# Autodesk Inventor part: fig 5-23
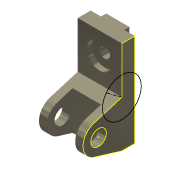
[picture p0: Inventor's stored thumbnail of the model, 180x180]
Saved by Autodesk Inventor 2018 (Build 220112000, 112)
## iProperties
Shininess: 65.0
Angle Display Precision: 2
Document Length Units: 11269
Document Angle Units: 11279
Document Time Units: 11290
Document Mass Units: 11283
Document Length Units Precision: 3
Document Angle Units Precision: 2
Compacted: False
Created: 2001-11
Part Number: fig 5-23
Document SubType Name: Modeling
Designer: Renu Muthoo
Density: 1 g/cm^3
Material: Generic
Appearance: Metal-Titanium (Polished)
Density: 0.0
Volumn: 0.0
Area: 0.0
PropertySet Name: Model Information
Control State: 0
Master: False
Checked Out: False
Author: Renu Muthoo
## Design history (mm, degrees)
node "Sketch1"
sketch "Sketch2"
  geometry: L1 (33.257, 104.664)-(33.257, -75.336); L2 (33.257, -75.336)-(8.257, -75.336); L3 (8.257, -75.336)-(-45.451, -59.045); L4 (-45.451, -1.628)-(8.257, 14.664); L5 (8.257, 14.664)-(8.257, 104.664); L6 (8.257, 104.664)-(33.257, 104.664); C1 r 15 at (-36.743, -30.336); A1 r 30 centre (-36.743, -30.336) between (-45.451, -1.628) and (-45.451, -59.045)
  constraints: 12 end point, 2 centre point, 2 equal length, 2 parallel, 2 point on circle, 2 tangent, 1 coincident, 1 perpendicular, 1 vertical
  dimensions: "d0" = 180 distance of L1.start L1.end; "d1" = 30 radius of A1; "d2" = 25 distance of L5.end L1.start; "d3" = 45 distance from line of L2 A1.centre; "d4" = 70 distance from line of L1 A1.centre; "d5" = 30 diameter of C1
extrude "Extrusion1" new body sketch "Sketch2" distance "d6" = 85; taper "d7" = 0 deg
workplane "Work Plane1"
sketch "Sketch3"
  geometry: L1 (15, 62.364)-(70, 62.364); L2 (70, 62.364)-(70, -52.386); L3 (70, -52.386)-(15, -52.386); L4 (15, -52.386)-(15, 62.364); L5 (0, -45)-(0, -28.708) reference
  constraints: 8 end point, 2 parallel, 1 horizontal, 1 perpendicular
  dimensions: "d8" = 55 distance of L1.start L1.end; "d9" = 15 distance between parallel lines of L5 L4
extrude "Extrusion2" cut sketch "Sketch3" distance "d10" = 50; taper "d11" = 0 deg
sketch "Sketch4"
  geometry: L1 (0, 25)-(85, 25) reference; L2 (0, 0)-(0, 25) reference; L3 (20, 25)-(65, 25); L4 (65, 25)-(65, 35); L5 (65, 35)-(20, 35); L6 (20, 35)-(20, 25)
  constraints: 8 end point, 2 parallel, 1 horizontal, 1 perpendicular, 1 point on line
  dimensions: "d12" = 45 distance of L4.end L5.end; "d13" = 10 distance of L3.end L4.end; "d14" = 20 distance between parallel lines of L2 L6
extrude "Extrusion3" join sketch "Sketch4" stored distance "d15" = 50; taper "d16" = 0 deg
sketch "Sketch5"
  geometry: L1 (85, 0)-(85, 90) reference; L2 (0, 90)-(85, 90) reference; 1 further point
  dimensions: "d17" = 42 distance from line of L2 point (42.5, 48); "d18" = 42.5 distance from line of L1 point (42.5, 48)
hole "Hole1" sketch "Sketch5" at (42.5, 48) diameter "d19" = 20; stored, may be unused: countersink angle "d23" = 82 deg, drill point angle "d25" = 118 deg; dims "d20" = 6, "d21" = 50, "d22" = 10, "d24" = 8
sketch "Sketch8"
  geometry: L1 (75.336, 33.257)-(75.336, 8.257) reference; L2 (-104.664, 33.257)-(75.336, 33.257) reference; L3 (-104.664, 8.257)-(-104.664, 33.257) reference; L4 (-14.664, 8.257)-(-104.664, 8.257) reference; L5 (1.628, -45.451)-(-14.664, 8.257) reference; L6 (75.336, 8.257)-(59.045, -45.451) reference; C1 r 15 at (30.336, -36.743) reference; C2 r 37.437 at (-14.664, 8.257); A1 r 30 centre (30.336, -36.743) between (1.628, -45.451) and (59.045, -45.451) reference
  constraints: 1 centre point, 1 coincident
sketch "Sketch9"
  geometry: L1 (75.336, 33.257)-(75.336, 8.257) reference; L2 (-14.664, 8.257)-(-104.664, 8.257) reference; L3 (1.628, -45.451)-(-14.664, 8.257) reference; L4 (75.336, 8.257)-(59.045, -45.451) reference; L5 (-14.664, 8.257)-(-37, -21.743); C1 r 15 at (30.336, -36.743) reference; A1 r 30 centre (30.336, -36.743) between (1.628, -45.451) and (59.045, -45.451) reference
  constraints: 2 end point
body "Solid1"
